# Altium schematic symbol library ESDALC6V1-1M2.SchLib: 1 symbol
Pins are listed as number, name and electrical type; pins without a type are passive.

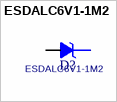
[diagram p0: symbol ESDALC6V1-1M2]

## ESDALC6V1-1M2
designator D?
footprint ST_SOD882T
pins: 1 K, 2 A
